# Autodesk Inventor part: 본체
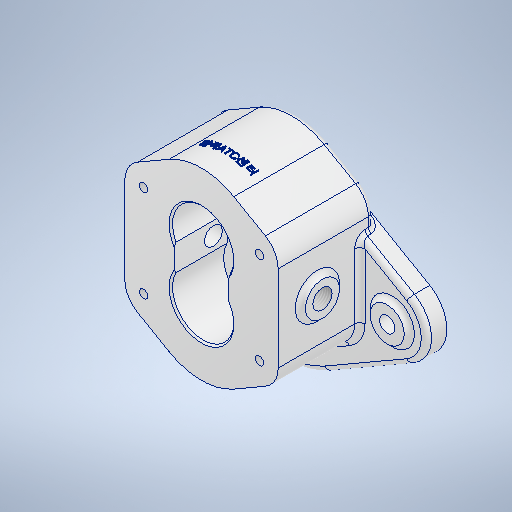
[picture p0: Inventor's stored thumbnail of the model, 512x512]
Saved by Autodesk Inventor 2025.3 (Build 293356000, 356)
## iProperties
Created: 2025-11
Part Number: 본체
Material: 알루미늄 6061
Document SubType Name: Modeling
Designer: PC-04
Density: 2.7 g/cm^3
Appearance: 알루미늄 - 평지
Mass: 1252.33 g
Surface Area: 588.016 cm^2
Volume: 463.826 cm^3
Author: PC-04
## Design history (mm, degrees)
sketch "스케치1"
  geometry: L1 (-45, 54)-(45, 54); L2 (45, 54)-(45, -54); L3 (45, -54)-(-45, -54); L4 (-45, -54)-(-45, 54); L5 (-45, 54)-(45, -54); L6 (45, 54)-(-45, -54); L7 (45, -33.898)-(19, -48.909); L8 (19, 48.909)-(45, 33.898); L9 (-45, 0)-(45, 0); L10 (0, 54)-(0, -54); L11 (-19, 48.909)-(-45, 33.898); L12 (-45, -33.898)-(-19, -48.909); A1 r 38 centre (0, -16) between (19, -48.909) and (0, -54); A2 r 38 centre (0, 16) between (19, 48.909) and (0, 54); 7 further points
  constraints: 24 end point, 6 midpoint, 4 point on circle, 4 symmetric about line, 2 centre point, 2 coincident, 2 parallel, 2 point on line, 2 tangent, 1 horizontal, 1 perpendicular
  dimensions: "d0" = 90 distance of L2.end L3.end; "d1" = 108 distance of L1.end L2.end; "d2" = 16 distance of point (0, 0) point (0, 16); "d3" = 16 distance of point (0, 0) point (0, -16); "d4" = 45 distance from line of L2 point (0, 16); "d5" = 45 distance from line of L2 point (0, -16); "d6" = 76 diameter of A1; "d7" = 76 diameter of A2; "d8" = 30 deg angle of L9 L8; "d9" = 30 deg angle of L9 L7
extrude "돌출1" new body sketch "스케치1" stored distance "d10" = 56; taper "d11" = 0 deg
fillet "모깎기1" dims "d12" = 15
sketch "스케치2"
  geometry: L1 (54, -28)-(-54, -28) reference; L2 (-54, -28)-(-54, 28) reference; L3 (-54, 28)-(54, 28) reference; L4 (54, 28)-(54, -28) reference; L5 (16, 28)-(16, -28); L6 (34, 27)-(34, -3); L7 (25.238, -28)-(25.238, 28) reference; L8 (34, -3)-(28.5, -3); L9 (27.5, -4)-(27.5, -18); L10 (27.5, -18)-(16, -18); L11 (35, 28)-(54, 28); L12 (35, 28)-(34, 27); L13 (28.5, -3)-(27.5, -4); 5 further points
  constraints: 16 end point, 8 point on line, 4 perpendicular, 1 collinear, 1 parallel
  dimensions: "d13" = 16 distance from line of point (0, 0) L5; "d14" = 15 distance between parallel lines of L8 L10; "d15" = 31 distance between parallel lines of L3 L8; "d16" = 36 diameter of L6 L5; "d17" = 23 diameter of L9 L5; "d18" = 1 distance of L11.start point (34, 28); "d19" = 1 distance of L6.start point (34, 28) (= d18); "d20" = 1 distance of L8.end point (27.5, -3) (= d18); "d21" = 1 distance of L9.start point (27.5, -3) (= d20)
revolve "회전1" sketch "스케치2" stored, may be unused: angle "d22" = 360 deg
sketch "스케치3"
  geometry: L1 (25.238, 28)-(-25.238, 28) reference; L2 (-16, 28)-(-16, -28); L3 (-25.238, -28)-(25.238, -28) reference; L4 (54, -28)-(-54, -28) reference; L5 (-54, -28)-(-54, 28) reference; L6 (-54, 28)-(-3, 28) reference; L7 (-3, 28)-(-2, 27) reference; L8 (-2, 27)-(-2, -3) reference; L9 (-2, -3)-(3.5, -3) reference; L10 (3.5, -3)-(4.5, -4) reference; L11 (4.5, -4)-(4.5, -18) reference; L12 (4.5, -18)-(27.5, -18) reference; L13 (27.5, -18)-(27.5, -4) reference; L14 (27.5, -4)-(28.5, -3) reference; L15 (28.5, -3)-(34, -3) reference; L16 (34, -3)-(34, 27) reference; L17 (34, 27)-(35, 28) reference; L18 (35, 28)-(54, 28) reference; L19 (54, 28)-(54, -28) reference; L20 (0, 28)-(0, -28); L21 (-35, 28)-(-54, 28); L22 (-34, 27)-(-35, 28); L23 (-34, -3)-(-34, 27); L24 (-28.5, -3)-(-34, -3); L25 (-27.5, -4)-(-28.5, -3); L26 (-27.5, -18)-(-27.5, -4); L27 (-4.5, -18)-(-27.5, -18); 3 further points
  constraints: 18 end point, 7 symmetric about line, 2 midpoint, 2 point on line, 1 vertical
  dimensions: "d23" = 16 distance from line of L2 point (0, 0)
revolve "회전2" sketch "스케치3" stored, may be unused: angle "d24" = 90 deg
sketch "스케치4"
  geometry: L1 (-16, 16)-(16, 16); L2 (16, 16)-(16, -16); L3 (16, -16)-(-16, -16); L4 (-16, -16)-(-16, 16); L5 (-16, 16)-(16, -16); L6 (16, 16)-(-16, -16); 1 further point
  constraints: 12 end point, 2 midpoint, 2 parallel, 1 horizontal, 1 perpendicular
  dimensions: "d25" = 32 distance of L2.end L3.end; "d26" = 32 distance of L1.end L2.end
extrude "돌출2" cut sketch "스케치4" distance "d27" = 31; taper "d28" = 0 deg
node "작업 평면1"
sketch "스케치5"
  geometry: L1 (-74, 1.321)-(-26, 29.033); L2 (-74, -33.321)-(-26, -61.033); L3 (26, -61.033)-(74, -33.321); L4 (74, 1.321)-(26, 29.033); C1 r 11.5 at (0, -16) reference; A1 r 52 centre (0, -16) between (-26, 29.033) and (-26, -61.033); A2 r 20 centre (-64, -16) between (-74, 1.321) and (-74, -33.321); A3 r 20 centre (64, -16) between (74, -33.321) and (74, 1.321); 2 further points
  constraints: 8 end point, 8 point on circle, 8 tangent, 3 centre point, 2 coincident, 2 horizontal alignment
  dimensions: "d32" = 104 diameter of A1; "d33" = 40 diameter of A2; "d34" = 40 diameter of A3; "d35" = 64 distance of point (0, -16) A3.centre; "d36" = 128 distance of A2.centre A3.centre
extrude "돌출3" join sketch "스케치5" distance "d37" = 12; taper "d38" = 0 deg
sketch "스케치7"
  geometry: C1 r 11.5 at (0, -16) reference; C2 r 25 at (0, -16); 1 further point
  constraints: 1 centre point, 1 coincident
  dimensions: "d46" = 50 diameter of C2
extrude "돌출4" join sketch "스케치7" distance "d47" = 4; taper "d48" = 0 deg
sketch "스케치8"
  geometry: L1 (-4.5, -18)-(-27.5, -18) reference; L2 (-16, -18)-(-16, -36); L3 (-41, -36)-(9, -36) reference; L4 (-5.5, -18)-(-5.5, -28.7); L5 (-5.5, -28.7)-(-1.3, -28.7); L6 (-1, -29)-(-1, -35.3); L7 (-0.596, -36)-(9, -36); L8 (-1, -35.3)-(-0.596, -36); A1 r 0.3 centre (-1.3, -29) between (-1, -29) and (-1.3, -28.7); 3 further points
  constraints: 12 end point, 4 point on line, 2 midpoint, 2 perpendicular, 2 point on circle, 2 tangent, 1 centre point, 1 collinear, 1 vertical
  dimensions: "d49" = 30 diameter of L6 L2; "d50" = 21 diameter of L4 L2; "d51" = 7.3 distance between parallel lines of L3 L5; "d52" = 0.3 radius of A1 (derived); "d53" = 0.7 distance of L6.end point (-1, -36); "d54" = 30 deg angle of L6 L8
revolve "회전4" sketch "스케치8" stored, may be unused: angle "d55" = 90 deg
sketch "스케치9"
  geometry: 1 further point
chamfer "모따기1" distance "d56" = 1; stored, may be unused: second distance "d57" = 2, angle "d58" = 45 deg
sketch "스케치10"
  geometry: L1 (0, 0)-(0, 50.475) reference; C1 r 10 at (23, 25.238); 2 further points
  constraints: 1 centre point, 1 coincident, 1 horizontal alignment
  dimensions: "d59" = 23 distance from line of L1 point (23, 25.238); "d60" = 20 diameter of C1
extrude "돌출5" join sketch "스케치10" distance "d61" = 3; taper "d62" = 0 deg
sketch "스케치11"
  geometry: L1 (-23, 25.238)-(33, 25.238) reference; 2 further points
  dimensions: "d63" = 5 distance of point (5, 0) point (0, 0); "d64" = 25.2376 distance from line of L1 point (0, 0)
hole "구멍1" sketch "스케치11" at (0, 0) diameter "d65" = 10.5; stored, may be unused: countersink angle "d71" = 90 deg, drill point angle "d73" = 0 deg; dims "d66" = 11, "d67" = 0.62479, "d68" = 10.589, "d69" = 4, "d70" = 2, "d72" = 17.5
sketch "스케치12"
  geometry: C1 r 10 at (64, -16); A1 r 20 centre (64, -16) between (74, -33.321) and (74, 1.321) reference; 1 further point
  constraints: 1 centre point, 1 coincident
  dimensions: "d74" = 20 diameter of C1
extrude "돌출6" join sketch "스케치12" distance "d75" = 3; taper "d76" = 0 deg
sketch "스케치13"
  geometry: L1 (-19, -9.238)-(-19, 41.238) reference; 2 further points
  dimensions: "d77" = 16 vertical distance of point (-64, 16) point (0, 0); "d78" = 19 distance from line of L1 point (0, 0)
hole "구멍2" sketch "스케치13" at (0, 0) diameter "d79" = 9; stored, may be unused: countersink angle "d83" = 90 deg, drill point angle "d85" = 0 deg; dims "d80" = 11, "d81" = 4, "d82" = 2, "d84" = 8
sketch "스케치14"
  geometry: L1 (-34, 27)-(34, 27); L2 (34, 27)-(34, -27); L3 (34, -27)-(-34, -27); L4 (-34, -27)-(-34, 27); L5 (-34, 27)-(34, -27); L6 (34, 27)-(-34, -27); 5 further points
  constraints: 12 end point, 4 coincident, 2 midpoint, 2 parallel, 1 horizontal, 1 perpendicular
  dimensions: "d86" = 68 distance of L2.end L3.end; "d87" = 54 distance of L1.end L2.end
hole "구멍3" sketch "스케치14" at (-34, 27), (34, 27), (34, -27), (-34, -27) diameter "d88" = 4.917; stored, may be unused: countersink angle "d92" = 90 deg, drill point angle "d94" = 118 deg; dims "d89" = 12, "d90" = 4, "d91" = 2, "d93" = 14
fillet "모깎기2" dims "d95" = 3
fillet "모깎기3" dims "d96" = 3
fillet "모깎기4" dims "d97" = 3
fillet "모깎기5" dims "d98" = 3
fillet "모깎기6" dims "d99" = 3
sketch "스케치15"
  geometry: L1 (-45, 28)-(-37.5, 28) reference; 2 further points
  constraints: 1 vertical alignment, 1 other
  dimensions: "d100" = 16 distance from line of L1 point (0, 12)
feature "엠보싱1" sketch "스케치15" dims "d0" = 90, "d1" = 108, "d2" = 16, "d3" = 16, "d4" = 45, "d5" = 45, "d6" = 76, "d7" = 76, "d8" = 30 deg, "d9" = 30 deg, "d101" = 0.5, "d102" = 0
node "솔리드1"
mirror "미러1"
mirror "미러2"
node "작업 평면2"
node "절단 모서리 투영1"
node "절단 모서리 투영2"
feature "A9D066F2-1C7D-4E18-AEED-F7BC21143FA4" dims "d79" = 9, "d80" = 11, "d81" = 4, "d82" = 2, "d83" = 90 deg, "d84" = 8, "d85" = 0
